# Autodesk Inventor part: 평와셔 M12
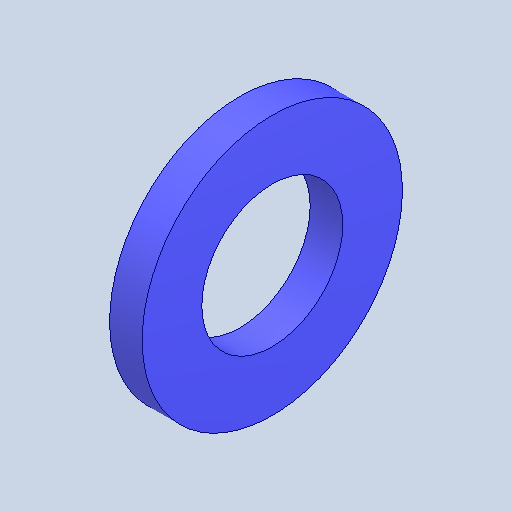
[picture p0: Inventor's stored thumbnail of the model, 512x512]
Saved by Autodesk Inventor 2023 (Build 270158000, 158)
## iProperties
Created: 2025-03
Part Number: 평와셔 M12
Material: 스테인리스강
Description: 평면 와셔
Document SubType Name: Modeling
Designer: Admin
Density: 8.08 g/cm^3
Appearance: 기본값
Author: jhkim
Sending System: Autodesk Inventor 2025
Preprocessor: ST-DEVELOPER v20
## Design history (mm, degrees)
feature "Solid1"
node "솔리드1"
